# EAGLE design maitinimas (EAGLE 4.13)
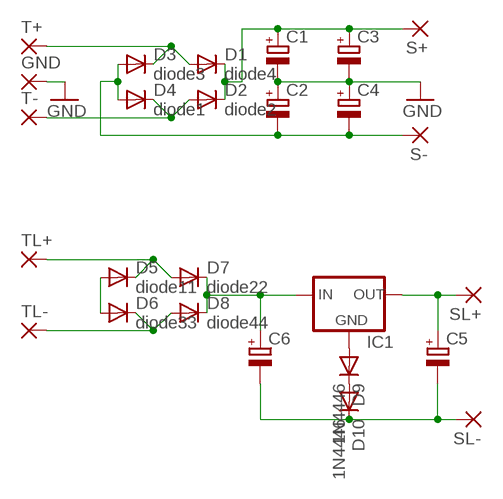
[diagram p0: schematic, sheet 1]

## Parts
C1  CPOL-EUE10-35  [EB35D]
C2  CPOL-EUE10-35  [EB35D]
C3  CPOL-EUE10-35  [EB35D]
C4  CPOL-EUE10-35  [EB35D]
C5  CPOL-EUE10-20  [EB20D]
C6  CPOL-EUE10-20  [EB20D]
D1  diode4  1N5624  [DO201-15]
D2  diode2  1N5624  [DO201-15]
D3  diode3  1N5624  [DO201-15]
D4  diode1  1N5624  [DO201-15]
D5  diode11  1N5624  [DO201-15]
D6  diode33  1N5624  [DO201-15]
D7  diode22  1N5624  [DO201-15]
D8  diode44  1N5624  [DO201-15]
D9  1N4446  [DO35-10]
D10  1N4446  [DO35-10]
GND  3,81/1,4  [3,81/1,4]
IC1  78XXS  [78XXS]
S+  3,81/1,4  [3,81/1,4]
S-  3,81/1,4  [3,81/1,4]
SL+  3,81/1,4  [3,81/1,4]
SL-  3,81/1,4  [3,81/1,4]
T+  3,81/1,4  [3,81/1,4]
T-  3,81/1,4  [3,81/1,4]
TL+  3,81/1,4  [3,81/1,4]
TL-  3,81/1,4  [3,81/1,4]

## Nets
GND: C1.- C2.+ C3.- C4.+ GND.1(P)
N$1: D5.C D7.A TL+.1(P)
N$2: C2.- C4.- D3.A D4.A S-.1(P)
N$3: D1.A D3.C T+.1(P)
N$4: D2.A D4.C T-.1(P)
N$5: C1.+ C3.+ D1.C D2.C S+.1(P)
N$6: D6.C D8.A TL-.1(P)
N$7: C6.+ D7.C D8.C IC1.IN
N$8: D5.A D6.A
N$9: D9.A IC1.GND
N$10: D9.C D10.A
N$11: C5.- C6.- D10.C SL-.1(P)
N$12: C5.+ IC1.OUT SL+.1(P)

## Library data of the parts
C1-C6 = rcl:CPOL-EU: POLARIZED CAPACITOR, European symbol
D1-D8 = diode:1N5624: DIODE
D9 D10 = diode:1N4446: DIODE
GND S+ S- SL+ SL- T+ T- TL+ TL- = wirepad:3,81/1,4: THROUGH-HOLE PAD
IC1 = v-reg:78XXS: VOLTAGE REGULATOR

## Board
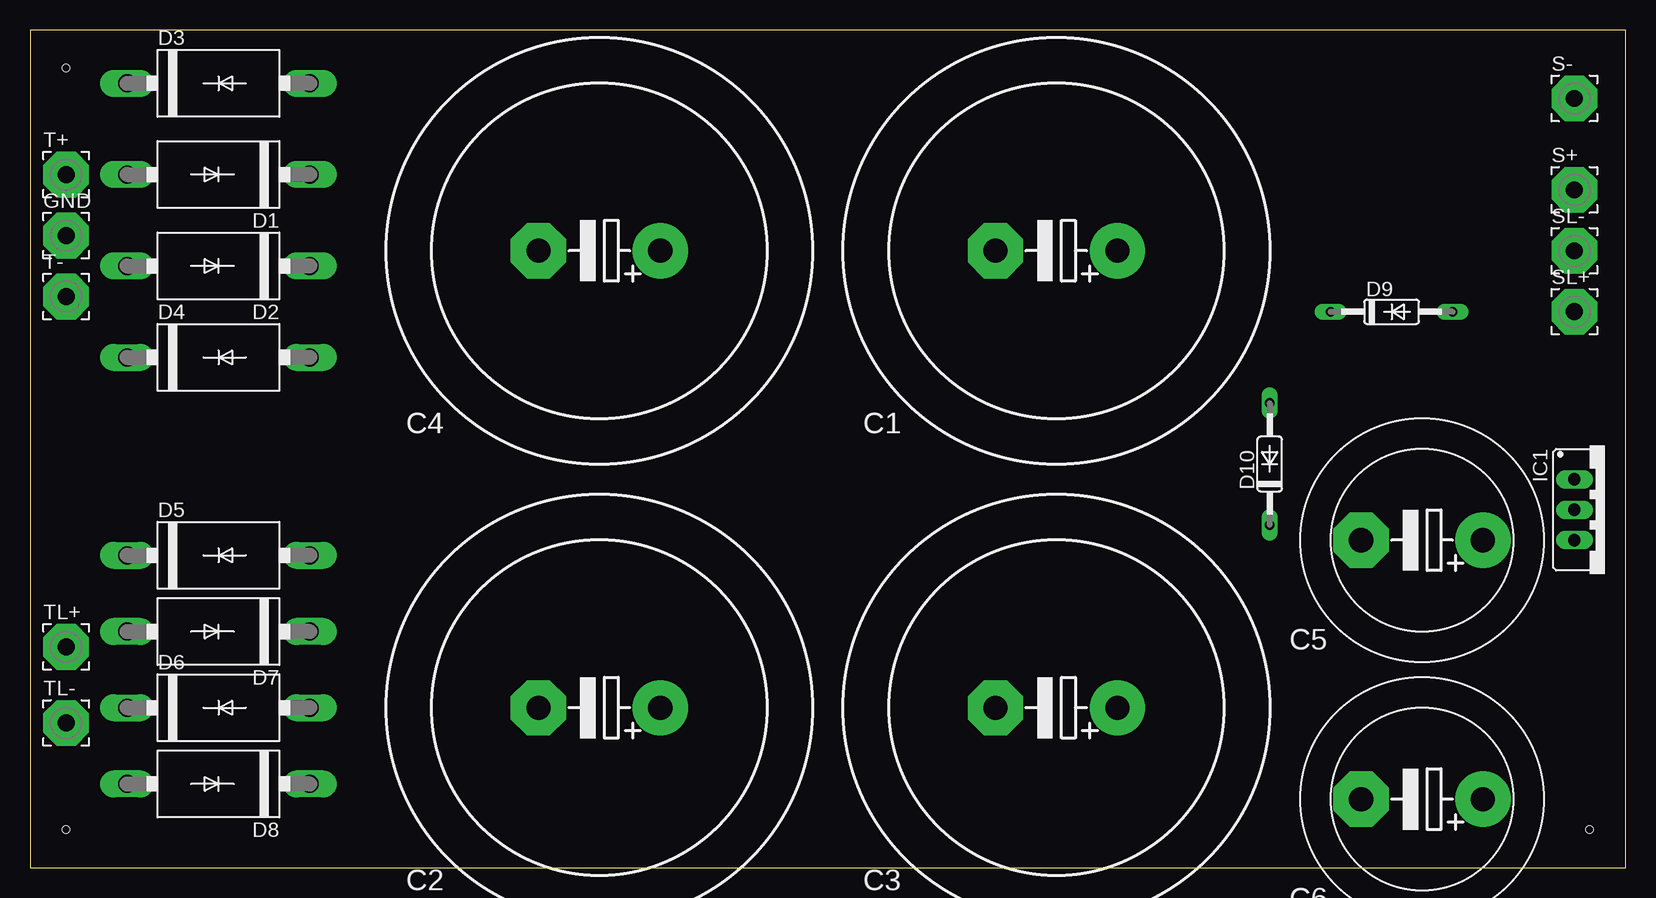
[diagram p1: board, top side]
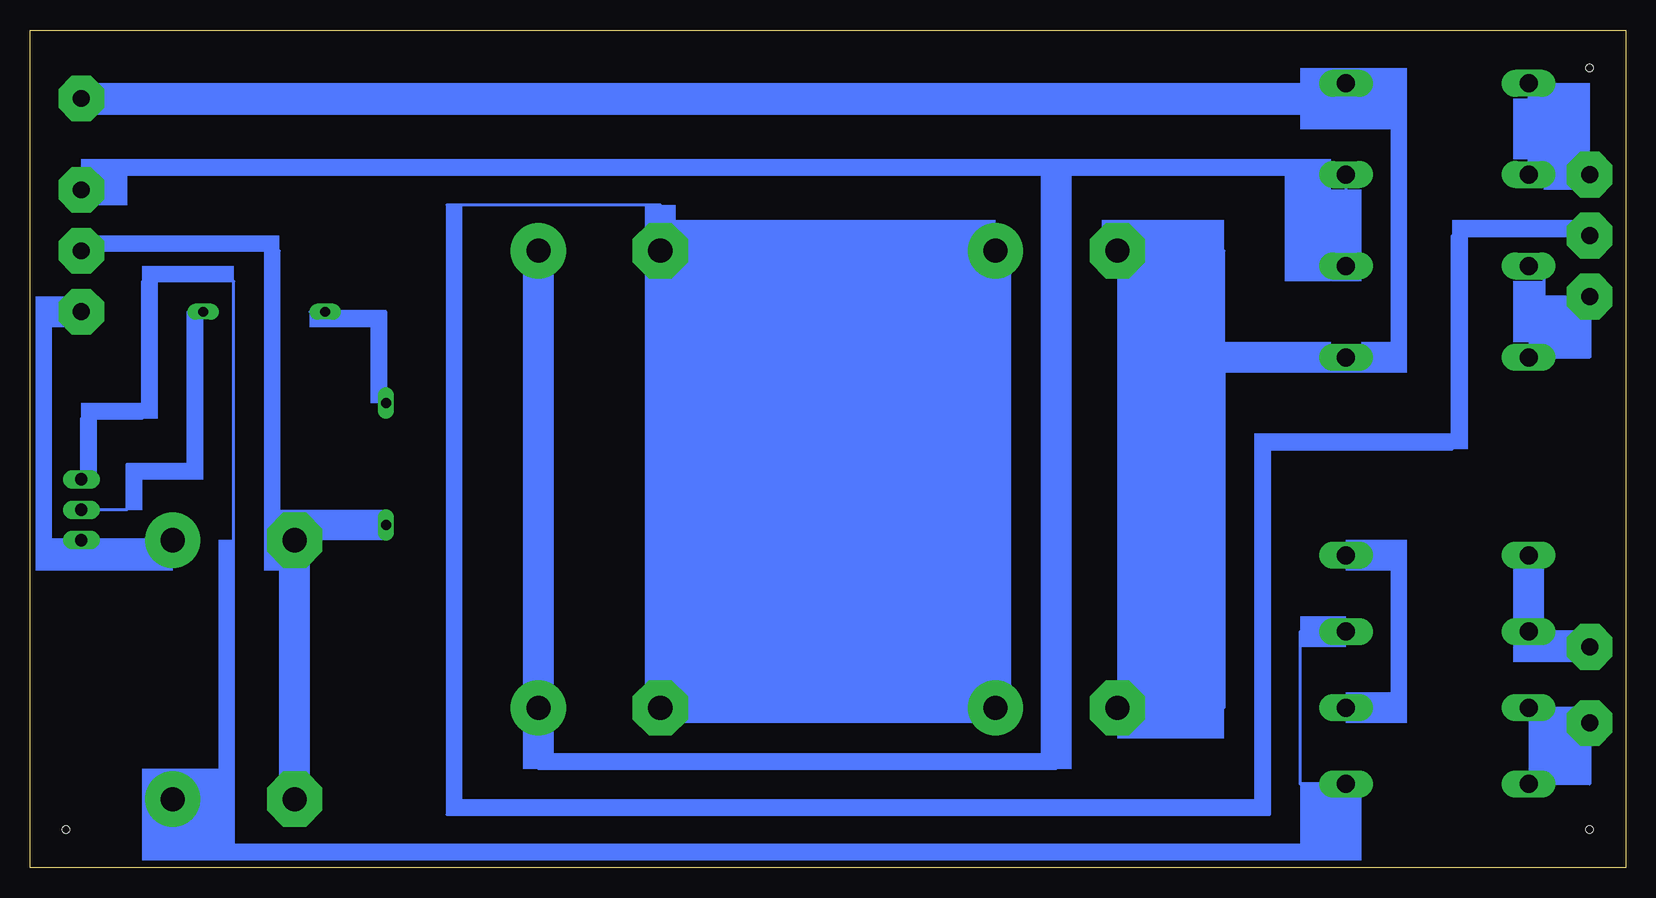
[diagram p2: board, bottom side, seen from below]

Size 133.02 x 69.84 mm. Coordinates in mm from the lower left corner, seen from the top.
Outline: 0,0 133.02,0 133.02,69.84 0,69.84 0,0
Copper layers (1*16): Top 0.035mm / dielectric 1.5mm / Bottom 0.035mm
Design rules "default": minimum track width 10mil, minimum drill 24mil, track to track 8mil, track to pad 8mil, pad to pad 8mil, via to via 8mil, smd to smd 8mil, copper to edge 40mil, drill to drill 8mil, minimum pad ring 10mil, minimum via ring 8mil, stop-mask expansion 4mil, vias tented up to drill 0mil, thermal gap 10mil
Holes 0.6 mm at 3.01,3.17 3.01,66.67 130.01,3.17

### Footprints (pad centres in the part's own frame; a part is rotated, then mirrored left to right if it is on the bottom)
EB35D = drill 2.007 pad 4.597 round: + -5.08,0 | drill 2.007 pad 4.597 octagon: - 5.08,0
EB20D = drill 2.007 pad 4.597 round: + -5.08,0 | drill 2.007 pad 4.597 octagon: - 5.08,0
DO201-15 = drill 1.499 long: A 7.62,0; C -7.62,0
DO35-10 = drill 0.813 long: A 5.08,0; C -5.08,0
3,81/1,4 = drill 1.397 pad 3.81 octagon: 1 0,0
78XXS = drill 1.016 long: GND 0,-2.54; IN -2.54,-2.54; OUT 2.54,-2.54

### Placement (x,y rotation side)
C1  85.56,51.43 180 top
C2  47.46,13.33 180 top
C3  85.56,13.33 180 top
C4  47.46,51.43 180 top
C5  116.04,27.3 180 top
C6  116.04,5.71 180 top
D1  15.71,57.78 180 top
D2  15.71,50.16 180 top
D3  15.71,65.4 0 top
D4  15.71,42.54 0 top
D5  15.71,26.03 0 top
D6  15.71,13.33 0 top
D7  15.71,19.68 180 top
D8  15.71,6.98 180 top
D9  113.5,46.35 0 top
D10  103.34,33.65 90 top
GND  3.01,52.7 0 top
IC1  131.28,29.84 270 top
S+  128.74,56.51 0 top
S-  128.74,64.13 0 top
SL+  128.74,46.35 0 top
SL-  128.74,51.43 0 top
T+  3.01,57.78 0 top
T-  3.01,47.62 0 top
TL+  3.01,18.41 0 top
TL-  3.01,12.06 0 top

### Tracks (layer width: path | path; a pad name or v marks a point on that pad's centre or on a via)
GND
  Bottom 0.254: C2.+ C3.- C1.- | GND.1 14.44,52.7 14.44,34.92 29.68,34.92 29.68,4.44 98.26,4.44 98.26,55.24 80.48,55.24 C1.- | C1.- C4.+
N$1
  Bottom 0.254: TL+.1 4.28,19.68 D7.A D5.C
N$2
  Bottom 0.254: 33.49,42.54 D4.A 19.52,42.54 19.52,62.86 | 33.49,42.54 33.49,13.33 C2.- | 19.52,62.86 19.52,65.4 D3.A | 33.49,42.54 33.49,51.43 C4.- | 19.52,62.86 127.47,62.86 S-.1
N$3
  Bottom 0.254: T+.1 D1.A D3.C
N$4
  Bottom 0.254: D4.C 3.01,42.54 T-.1 6.82,47.62 6.82,50.16 D2.A
N$5
  Bottom 0.254: D2.C D1.C 47.46,57.78 | C1.+ C3.+ 89.37,12.06 90.64,12.06 90.64,8.25 47.46,8.25 47.46,57.78 | 47.46,57.78 127.47,57.78 S+.1
N$6
  Bottom 0.254: D8.A 3.01,6.98 TL-.1 4.28,13.33 D6.C
N$7
  Bottom 0.254: D7.C 27.14,19.68 27.14,6.98 D8.C 23.33,1.9 116.04,1.9 | 116.04,1.9 121.12,1.9 C6.+ | 116.04,1.9 116.04,48.89 123.66,48.89 123.66,37.46 128.74,37.46 IC1.IN
N$8
  Bottom 0.254: D6.A 19.52,13.33 19.52,26.03 D5.A
N$9
  Bottom 0.254: D9.A 119.85,46.35 119.85,33.65 124.93,33.65 124.93,29.84 IC1.GND
N$10
  Bottom 0.254: D10.A 103.34,46.35 D9.C 109.69,46.35
N$11
  Bottom 0.254: 109.69,6.98 C6.- C5.- | D10.C 109.69,28.57 C5.- | SL-.1 112.23,51.43 112.23,28.57 C5.-
N$12
  Bottom 0.254: C5.+ IC1.OUT 131.28,27.3 131.28,46.35 SL+.1
(copper drawn outside any net)
  shapes: Bottom area x83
